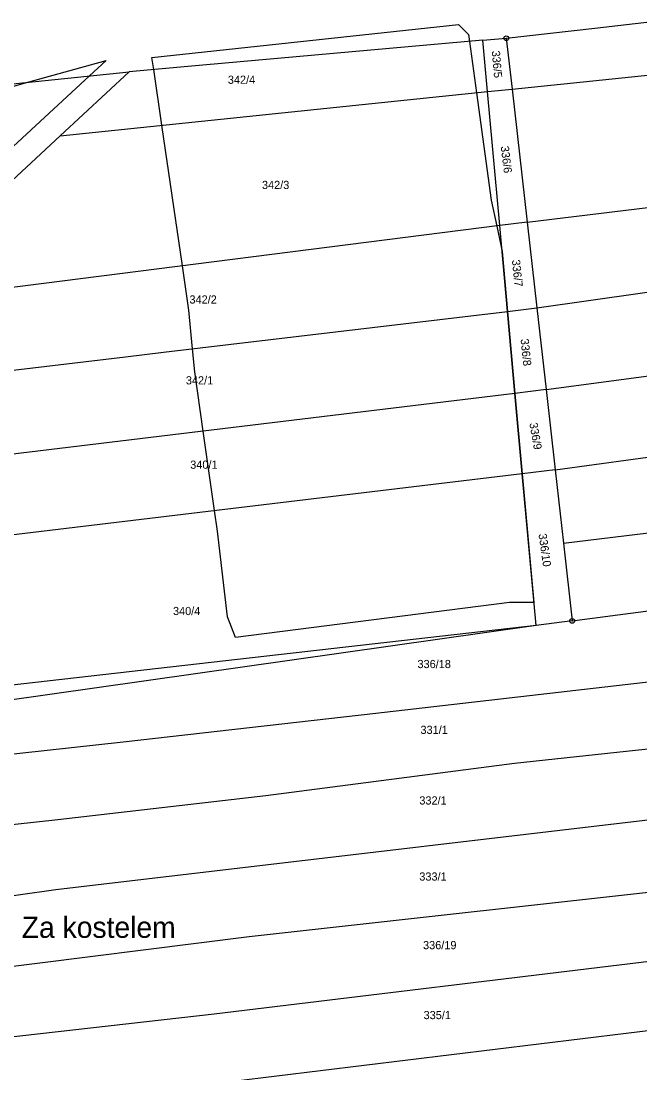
# Model space of a CAD drawing. Extents: x -747333 to -745433, y -1133152 to -1130600.
# Drawn here: x -746112.5 to -745983.7, y -1131861.6 to -1131642.6 of the extents above; entities that cross this region are included whole.
import ezdxf

# ---------------------------------------------------------------- set-up
doc = ezdxf.new("R2010")
doc.units = 0
for name, color, linetype in [('Vrstva 1', 7, 'Continuous'), ('Vrstva 15', 7, 'Continuous'), ('Vrstva 18', 7, 'Continuous'), ('Vrstva 24', 7, 'Continuous'), ('Vrstva 52', 7, 'Continuous'), ('Vrstva 6', 7, 'Continuous')]:
    doc.layers.add(name, color=color, linetype=linetype)

msp = doc.modelspace()

# ---------------------------------------------------------------- linework, layer by layer
at = {"layer": 'Vrstva 1'}
msp.add_line((-746133.92, -1131693.84), (-746104.37, -1131666.43), dxfattribs=at)
for points in [[(-745993.09, -1131644.03), (-745877.4, -1131630.6)], [(-746011.54, -1131646.14), (-745993.09, -1131644.03)], [(-746016.41, -1131646.56), (-746078.61, -1131652.1)], [(-746016.41, -1131646.56), (-746011.54, -1131646.14)], [(-746015.44, -1131657.26), (-746016.41, -1131646.56)], [(-746011.54, -1131646.14), (-746010.34, -1131656.73)], [(-746078.61, -1131652.1), (-746090.01, -1131653.11)], [(-746125.11, -1131656.77), (-746090.01, -1131653.11)], [(-746090.01, -1131653.11), (-746104.37, -1131666.43)], [(-746015.44, -1131657.26), (-746010.34, -1131656.73)], [(-746010.34, -1131656.73), (-746007.21, -1131684.44)], [(-746104.37, -1131666.43), (-746015.44, -1131657.26)], [(-746012.9, -1131685.16), (-746015.44, -1131657.26)], [(-746012.9, -1131685.16), (-746119.9, -1131698.71)], [(-746007.21, -1131684.44), (-746012.9, -1131685.16)], [(-746011.28, -1131703.02), (-746012.9, -1131685.16)], [(-746007.21, -1131684.44), (-746005.19, -1131702.3)], [(-746011.28, -1131703.02), (-746005.19, -1131702.3)], [(-746005.19, -1131702.3), (-746003.27, -1131719.29)], [(-746082.88, -1131711.52), (-746011.28, -1131703.02)], [(-746009.74, -1131720.07), (-746011.28, -1131703.02)], [(-746090.83, -1131712.46), (-746082.88, -1131711.52)], [(-746118.38, -1131715.73), (-746090.83, -1131712.46)], [(-746009.74, -1131720.07), (-746123.47, -1131733.84)], [(-746003.27, -1131719.29), (-746009.74, -1131720.07)], [(-746008.22, -1131736.82), (-746009.74, -1131720.07)], [(-746003.27, -1131719.29), (-746001.38, -1131736)], [(-746008.22, -1131736.82), (-746134.41, -1131751.93)], [(-746001.38, -1131736), (-746008.22, -1131736.82)], [(-746005.35, -1131768.4), (-746008.22, -1131736.82)], [(-746001.38, -1131736), (-745999.66, -1131751.26)], [(-745999.66, -1131751.26), (-745997.83, -1131767.45)], [(-746005.35, -1131768.4), (-746157.45, -1131789.98)], [(-746005.35, -1131768.4), (-746154.67, -1131785.39)], [(-745997.83, -1131767.45), (-746005.35, -1131768.4)]]:
    msp.add_lwpolyline(points, dxfattribs=at)
at = {"layer": 'Vrstva 24'}
for p, q in [((-746011.59, -1131646.14), (-746011.49, -1131646.14)), ((-745997.88, -1131767.45), (-745997.78, -1131767.45))]:
    msp.add_line(p, q, dxfattribs=at)
for centre in [(-746011.54, -1131646.14), (-745997.83, -1131767.45)]:
    msp.add_circle(centre, 0.499289, dxfattribs=at)
at = {"layer": 'Vrstva 52'}
for points in [[(-746085.31, -1131650.13), (-746021.5, -1131643.25), (-746019.38, -1131645.38), (-746019.18, -1131646.81), (-746017.73, -1131657.5), (-746014.69, -1131679.87), (-746013.54, -1131685.24), (-746012.41, -1131690.55), (-746011.28, -1131703.02), (-746009.74, -1131720.07), (-746008.22, -1131736.82), (-746005.78, -1131763.63), (-746010.88, -1131763.63)], [(-746010.88, -1131763.63), (-746067.88, -1131770.88), (-746069.56, -1131766.63), (-746071.69, -1131748.75), (-746072.29, -1131744.49), (-746074.63, -1131727.93), (-746076.38, -1131715.62), (-746076.84, -1131710.8), (-746077.62, -1131702.75), (-746078.97, -1131693.53), (-746083.25, -1131664.25), (-746084.94, -1131652.66), (-746085.31, -1131650.13)], [(-746191.62, -1131786.12), (-746198.87, -1131787.5), (-746195.98, -1131780.37), (-746190.37, -1131766.55), (-746184.18, -1131751.31), (-746184, -1131750.88), (-746183.66, -1131750.33), (-746146.96, -1131691.87), (-746144.38, -1131687.76), (-746141, -1131682.38), (-746131.25, -1131666.25), (-746128.68, -1131663.08), (-746125.69, -1131659.37), (-746111.15, -1131655.31), (-746094.81, -1131650.75), (-746098.31, -1131653.98)], [(-746098.31, -1131653.98), (-746138.57, -1131691.14), (-746140.19, -1131692.62), (-746139.75, -1131698.13), (-746135.99, -1131724.39), (-746133.87, -1131739.22), (-746132.55, -1131748.44), (-746132.5, -1131748.77), (-746132.09, -1131751.65), (-746128.25, -1131778.5), (-746152.36, -1131781.56), (-746186.69, -1131785.93), (-746188.25, -1131786.12), (-746191.62, -1131786.12)]]:
    msp.add_lwpolyline(points, dxfattribs=at)
at = {"layer": 'Vrstva 6'}
for points in [[(-746010.34, -1131656.73), (-745876.7, -1131642.95)], [(-746007.21, -1131684.44), (-745875.94, -1131668.46)], [(-746005.19, -1131702.3), (-745950.93, -1131694.59)], [(-746003.27, -1131719.29), (-745939.15, -1131710.71)], [(-746001.38, -1131736), (-745944.57, -1131728.25)], [(-745999.66, -1131751.26), (-745938.57, -1131743.81)], [(-745997.83, -1131767.45), (-745932.36, -1131758.79)], [(-746038.67, -1131786.65), (-745913.22, -1131772.23)], [(-746009.82, -1131797.07), (-745872.32, -1131782.29)], [(-746091.32, -1131792.64), (-746038.67, -1131786.65)], [(-746145.12, -1131798.49), (-746091.32, -1131792.64)], [(-746061.62, -1131803.78), (-746009.82, -1131797.07)], [(-746105.32, -1131823.34), (-745952.05, -1131805.35)], [(-746104.87, -1131808.78), (-746061.62, -1131803.78)], [(-746145.54, -1131813.2), (-746104.87, -1131808.78)], [(-746065.09, -1131833.14), (-745871.36, -1131811.65)], [(-746144.56, -1131828.9), (-746105.32, -1131823.34)], [(-746119.75, -1131839.99), (-746065.09, -1131833.14)], [(-746072.36, -1131849.26), (-745979.48, -1131837.99)], [(-746138, -1131856.68), (-746072.36, -1131849.26)], [(-746068.37, -1131863.25), (-745959.35, -1131849.97)]]:
    msp.add_lwpolyline(points, dxfattribs=at)

# ---------------------------------------------------------------- texts
at = {"layer": 'Vrstva 15'}
msp.add_text('Za kostelem', height=4.4, dxfattribs=at).set_placement((-746112.400161, -1131833.43))
at = {"layer": 'Vrstva 18'}
for s, rotation, p in [('336/5', 275.1282, (-746014.58, -1131648.81)), ('336/6', 276.86808, (-746012.71, -1131668.67)), ('336/7', 275.92065, (-746010.38, -1131692.32)), ('336/8', 275.73093, (-746008.57, -1131708.78)), ('336/9', 279.95256, (-746006.75, -1131726.31)), ('336/10', 278.15688, (-746004.85, -1131749.37))]:
    msp.add_text(s, height=1.7, rotation=rotation, dxfattribs=at).set_placement(p)
for s, p in [('342/4', (-746069.5, -1131655.63)), ('342/3', (-746062.4, -1131677.53)), ('342/2', (-746077.49, -1131701.38)), ('342/1', (-746078.24, -1131718.21)), ('340/1', (-746077.33, -1131735.77)), ('340/4', (-746080.92, -1131766.23)), ('336/18', (-746030.03, -1131777.27)), ('331/1', (-746029.41, -1131790.97)), ('332/1', (-746029.64, -1131805.67)), ('333/1', (-746029.65, -1131821.51)), ('336/19', (-746028.87, -1131835.79)), ('335/1', (-746028.76, -1131850.35))]:
    msp.add_text(s, height=1.7, dxfattribs=at).set_placement(p)

doc.saveas('drawing.dxf')
